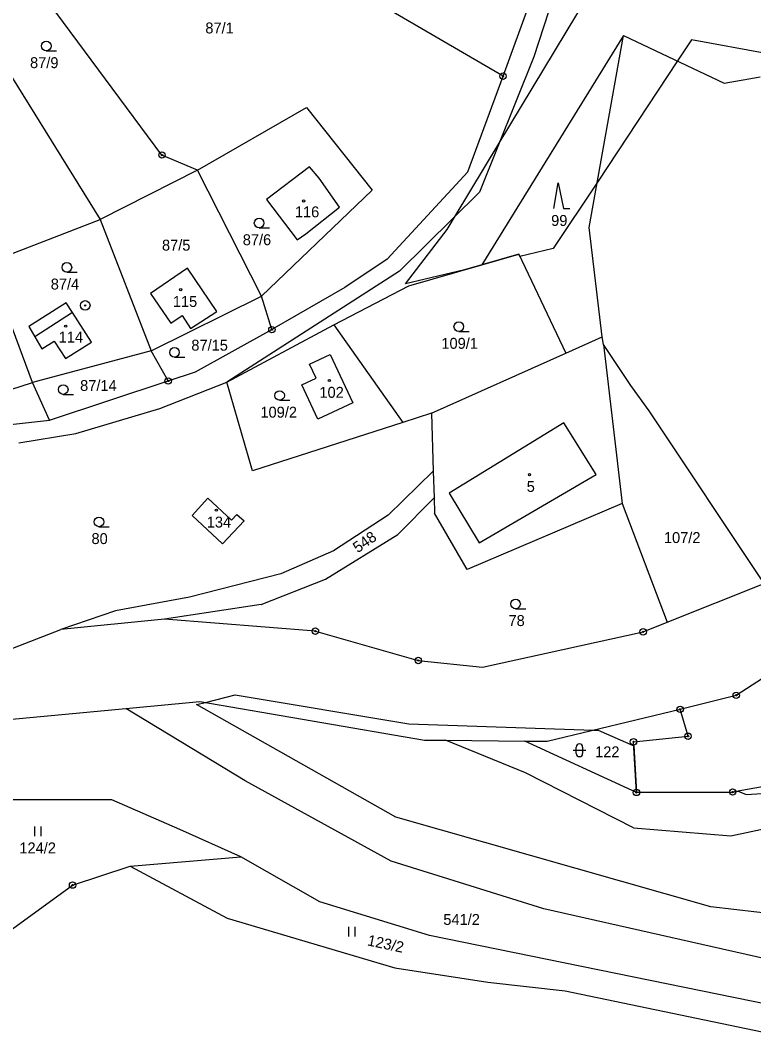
# Model space of a CAD drawing. Extents: x -547623 to -538651, y -1096714 to -1086522.
# Drawn here: x -544594.9 to -544480.8, y -1094558.3 to -1094399.5 of the extents above; entities that cross this region are included whole.
import ezdxf

# ---------------------------------------------------------------- set-up
doc = ezdxf.new("R2010")
doc.units = 0
for name, color, linetype in [('Vrstva 1', 7, 'Continuous'), ('Vrstva 25', 7, 'Continuous'), ('Vrstva 33', 7, 'Continuous'), ('Vrstva 52', 7, 'Continuous'), ('Vrstva 83', 7, 'Continuous'), ('Vrstva 86', 7, 'Continuous'), ('Vrstva 90', 7, 'Continuous'), ('Vrstva 92', 7, 'Continuous')]:
    doc.layers.add(name, color=color, linetype=linetype)

msp = doc.modelspace()

# ---------------------------------------------------------------- linework, layer by layer
at = {"layer": 'Vrstva 1'}
for points in [[(-544519.82, -1094408.15), (-544584.34, -1094370.53)], [(-544572.89, -1094420.43), (-544608.01, -1094373.06)], [(-544610.79, -1094384.91), (-544582.52, -1094430.48)], [(-544509.63, -1094388.53), (-544515.03, -1094405.12)], [(-544519.82, -1094408.15), (-544515.7, -1094396.87)], [(-544501.07, -1094401.8), (-544523.11, -1094437.52)], [(-544506.4, -1094431.69), (-544501.07, -1094401.8)], [(-544501.07, -1094401.8), (-544485.43, -1094409.22)], [(-544515.03, -1094405.12), (-544523.46, -1094426.21)], [(-544525.28, -1094423.07), (-544519.82, -1094408.15)], [(-544485.43, -1094409.22), (-544479.78, -1094408.26)], [(-544567.38, -1094422.79), (-544550.42, -1094413.01)], [(-544550.42, -1094413.01), (-544540.19, -1094425.9)], [(-544567.38, -1094422.79), (-544572.89, -1094420.43)], [(-544567.38, -1094422.79), (-544582.52, -1094430.48)], [(-544557.38, -1094442.38), (-544567.38, -1094422.79)], [(-544549.91, -1094422.26), (-544556.64, -1094427.34)], [(-544548.44, -1094424.01), (-544549.91, -1094422.26)], [(-544525.28, -1094423.07), (-544537.85, -1094436.64)], [(-544545.26, -1094428.53), (-544548.44, -1094424.01)], [(-544540.19, -1094425.9), (-544557.38, -1094442.38)], [(-544523.46, -1094426.21), (-544535.95, -1094438.49)], [(-544556.64, -1094427.34), (-544551.83, -1094433.64)], [(-544550.48, -1094432.72), (-544545.26, -1094428.53)], [(-544600.01, -1094437.2), (-544582.52, -1094430.48)], [(-544582.52, -1094430.48), (-544574.56, -1094450.91)], [(-544551.83, -1094433.64), (-544550.48, -1094432.72)], [(-544504.39, -1094448.76), (-544506.4, -1094431.69)], [(-544523.11, -1094437.52), (-544517.36, -1094435.86)], [(-544517.36, -1094435.86), (-544510.02, -1094451.27)], [(-544593.06, -1094455.85), (-544600.01, -1094437.2)], [(-544537.85, -1094436.64), (-544544.41, -1094441.05)], [(-544534.46, -1094440.81), (-544523.11, -1094437.52)], [(-544568.91, -1094438.07), (-544574.7, -1094442.01)], [(-544564.37, -1094444.77), (-544568.91, -1094438.07)], [(-544535.95, -1094438.49), (-544562.82, -1094455.78)], [(-544544.41, -1094441.05), (-544555.78, -1094447.62)], [(-544546.15, -1094446.85), (-544534.46, -1094440.81)], [(-544574.7, -1094442.01), (-544571.52, -1094446.62)], [(-544574.56, -1094450.91), (-544557.38, -1094442.38)], [(-544555.78, -1094447.62), (-544557.38, -1094442.38)], [(-544587.81, -1094443.46), (-544593.59, -1094447.13)], [(-544586.83, -1094444.97), (-544587.81, -1094443.46)], [(-544583.85, -1094449.59), (-544586.83, -1094444.97)], [(-544571.52, -1094446.62), (-544569.77, -1094445.43)], [(-544569.77, -1094445.43), (-544568.44, -1094447.46)], [(-544568.44, -1094447.46), (-544564.37, -1094444.77)], [(-544593.59, -1094447.13), (-544592.67, -1094448.72)], [(-544562.82, -1094455.78), (-544546.15, -1094446.85)], [(-544546.15, -1094446.85), (-544535.41, -1094462.05)], [(-544592.67, -1094448.72), (-544591.57, -1094450.61)], [(-544567.68, -1094454.21), (-544555.78, -1094447.62)], [(-544510.02, -1094451.27), (-544504.39, -1094448.76)], [(-544504.21, -1094449.91), (-544504.39, -1094448.76)], [(-544591.57, -1094450.61), (-544589.66, -1094449.42)], [(-544589.66, -1094449.42), (-544587.9, -1094452.11)], [(-544587.9, -1094452.11), (-544583.85, -1094449.59)], [(-544499.92, -1094456.3), (-544504.21, -1094449.91)], [(-544504.21, -1094449.91), (-544501.27, -1094474.71)], [(-544574.56, -1094450.91), (-544593.06, -1094455.85)], [(-544571.92, -1094455.61), (-544574.56, -1094450.91)], [(-544549.93, -1094452.99), (-544546.71, -1094451.49)], [(-544546.71, -1094451.49), (-544543.2, -1094459.01)], [(-544530.93, -1094460.6), (-544510.02, -1094451.27)], [(-544548.91, -1094455.17), (-544549.93, -1094452.99)], [(-544571.92, -1094455.61), (-544567.68, -1094454.21)], [(-544551.13, -1094456.2), (-544548.91, -1094455.17)], [(-544611.09, -1094461.67), (-544593.06, -1094455.85)], [(-544590.39, -1094461.72), (-544593.06, -1094455.85)], [(-544590.39, -1094461.72), (-544571.92, -1094455.61)], [(-544573.24, -1094459.92), (-544562.82, -1094455.78)], [(-544558.82, -1094469.62), (-544562.82, -1094455.78)], [(-544548.64, -1094461.55), (-544551.13, -1094456.2)], [(-544497.09, -1094460.28), (-544499.92, -1094456.3)], [(-544586.29, -1094463.78), (-544573.24, -1094459.92)], [(-544543.2, -1094459.01), (-544548.64, -1094461.55)], [(-544530.93, -1094460.6), (-544535.41, -1094462.05)], [(-544530.93, -1094460.6), (-544530.67, -1094469.65)], [(-544479.2, -1094487.13), (-544497.09, -1094460.28)], [(-544604.47, -1094463.25), (-544590.39, -1094461.72)], [(-544535.41, -1094462.05), (-544558.82, -1094469.62)], [(-544595.15, -1094465.22), (-544586.29, -1094463.78)], [(-544530.67, -1094469.65), (-544537.69, -1094476.48)], [(-544530.67, -1094469.65), (-544530.56, -1094473.81)], [(-544568.17, -1094476.55), (-544565.75, -1094473.86)], [(-544565.75, -1094473.86), (-544562.08, -1094477.29)], [(-544536.2, -1094479.53), (-544530.56, -1094473.81)], [(-544530.56, -1094473.81), (-544530.49, -1094476.2)], [(-544501.27, -1094474.71), (-544525.42, -1094484.97)], [(-544501.27, -1094474.71), (-544494.29, -1094493.18)], [(-544563.48, -1094480.98), (-544568.17, -1094476.55)], [(-544560.11, -1094477.38), (-544563.48, -1094480.98)], [(-544562.08, -1094477.29), (-544561.25, -1094476.38)], [(-544561.25, -1094476.38), (-544560.11, -1094477.38)], [(-544537.69, -1094476.48), (-544546.19, -1094482.05)], [(-544525.42, -1094484.97), (-544530.49, -1094476.2)], [(-544547.46, -1094486.48), (-544536.2, -1094479.53)], [(-544546.19, -1094482.05), (-544554.42, -1094485.66)], [(-544554.42, -1094485.66), (-544568.59, -1094489.25)], [(-544557.46, -1094490.39), (-544547.46, -1094486.48)], [(-544494.29, -1094493.18), (-544479.2, -1094487.13)], [(-544568.59, -1094489.25), (-544580.11, -1094491.42)], [(-544580.11, -1094491.42), (-544588.64, -1094494.3)], [(-544557.46, -1094490.39), (-544572.49, -1094492.71)], [(-544572.49, -1094492.71), (-544588.64, -1094494.3)], [(-544549.02, -1094494.56), (-544572.49, -1094492.71)], [(-544498.01, -1094494.67), (-544494.29, -1094493.18)], [(-544609.47, -1094502.39), (-544588.64, -1094494.3)], [(-544549.02, -1094494.56), (-544533, -1094499.13)], [(-544522.99, -1094500.19), (-544498.01, -1094494.67)], [(-544483.53, -1094504.55), (-544472.85, -1094497.6)], [(-544533, -1094499.13), (-544522.99, -1094500.19)], [(-544492.26, -1094506.73), (-544483.53, -1094504.55)], [(-544578.51, -1094506.58), (-544567.02, -1094505.49)], [(-544567.02, -1094505.49), (-544532.04, -1094511.53)], [(-544598.49, -1094508.48), (-544578.51, -1094506.58)], [(-544559.95, -1094517.84), (-544578.51, -1094506.58)], [(-544512.96, -1094511.71), (-544492.26, -1094506.73)], [(-544491.03, -1094510.92), (-544492.26, -1094506.73)], [(-544499.51, -1094511.79), (-544491.03, -1094510.92)], [(-544532.04, -1094511.53), (-544528.77, -1094511.56)], [(-544516.31, -1094516.64), (-544528.77, -1094511.56)], [(-544528.77, -1094511.56), (-544516.44, -1094511.68)], [(-544499.06, -1094519.67), (-544516.44, -1094511.68)], [(-544516.44, -1094511.68), (-544512.96, -1094511.71)], [(-544499.06, -1094519.67), (-544499.51, -1094511.79)], [(-544460.91, -1094515.46), (-544484.09, -1094519.61)], [(-544499.5, -1094525.18), (-544516.31, -1094516.64)], [(-544537.25, -1094530.35), (-544559.95, -1094517.84)], [(-544484.09, -1094519.61), (-544499.06, -1094519.67)], [(-544580.7, -1094520.84), (-544598.37, -1094520.83)], [(-544570.11, -1094525.43), (-544580.7, -1094520.84)], [(-544484.38, -1094526.41), (-544456.89, -1094520.54)], [(-544499.5, -1094525.18), (-544484.38, -1094526.41)], [(-544560.61, -1094529.69), (-544570.11, -1094525.43)], [(-544577.85, -1094531.16), (-544560.61, -1094529.69)], [(-544548.33, -1094536.7), (-544560.61, -1094529.69)], [(-544586.8, -1094534.1), (-544577.85, -1094531.16)], [(-544577.85, -1094531.16), (-544562.76, -1094539.23)], [(-544513.47, -1094537.82), (-544537.25, -1094530.35)], [(-544596.14, -1094540.91), (-544586.8, -1094534.1)], [(-544531.27, -1094541.95), (-544548.33, -1094536.7)], [(-544473.96, -1094546.71), (-544513.47, -1094537.82)], [(-544562.76, -1094539.23), (-544536.63, -1094546.98)], [(-544470.45, -1094554.36), (-544531.27, -1094541.95)], [(-544536.63, -1094546.98), (-544522.17, -1094549.23)], [(-544522.17, -1094549.23), (-544510.16, -1094550.54)], [(-544510.16, -1094550.54), (-544472.99, -1094558.31)]]:
    msp.add_lwpolyline(points, dxfattribs=at)
at = {"layer": 'Vrstva 25'}
for p, q in [((-544590.9, -1094404.2), (-544589.3, -1094404.2)), ((-544557.77, -1094431.77), (-544556.17, -1094431.77)), ((-544587.69, -1094438.67), (-544586.09, -1094438.67)), ((-544526.7, -1094447.9), (-544525.1, -1094447.9)), ((-544570.94, -1094451.9), (-544569.34, -1094451.9)), ((-544588.26, -1094457.69), (-544586.66, -1094457.69)), ((-544554.59, -1094458.62), (-544552.99, -1094458.62)), ((-544582.7, -1094478.3), (-544581.1, -1094478.3)), ((-544517.87, -1094491.07), (-544516.27, -1094491.07)), ((-544508.93, -1094513.1), (-544506.93, -1094513.1)), ((-544508.43, -1094513.6), (-544508.43, -1094512.6)), ((-544507.43, -1094512.6), (-544507.43, -1094513.6)), ((-544592.67, -1094526.46), (-544592.67, -1094524.96)), ((-544591.67, -1094526.46), (-544591.67, -1094524.96)), ((-544543.81, -1094542.11), (-544543.81, -1094540.61)), ((-544542.81, -1094542.11), (-544542.81, -1094540.61))]:
    msp.add_line(p, q, dxfattribs=at)
msp.add_lwpolyline([(-544511.92, -1094428.77), (-544511.22, -1094424.77), (-544510.42, -1094428.77), (-544509.42, -1094428.77)], dxfattribs=at)
for centre, radius in [((-544590.9, -1094403.45), 0.75), ((-544550.85, -1094427.58), 0.175), ((-544557.77, -1094431.02), 0.75), ((-544587.69, -1094437.92), 0.75), ((-544569.97, -1094441.38), 0.175), ((-544587.87, -1094447.08), 0.175), ((-544526.7, -1094447.15), 0.75), ((-544570.94, -1094451.15), 0.75), ((-544588.26, -1094456.94), 0.75), ((-544546.83, -1094455.53), 0.175), ((-544554.59, -1094457.87), 0.75), ((-544515.7, -1094470.18), 0.175), ((-544564.42, -1094475.73), 0.175), ((-544582.7, -1094477.55), 0.75), ((-544517.87, -1094490.32), 0.75)]:
    msp.add_circle(centre, radius, dxfattribs=at)
for centre, start, end in [((-544507.93, -1094512.6), 0, 180), ((-544507.93, -1094513.6), 180, 0)]:
    msp.add_arc(centre, 0.5, start, end, dxfattribs=at)
at = {"layer": 'Vrstva 33'}
for points in [[(-544586.83, -1094444.97), (-544592.67, -1094448.72)], [(-544510.38, -1094462.15), (-544528.21, -1094473.1)], [(-544505.35, -1094470.19), (-544510.38, -1094462.15)], [(-544523.53, -1094480.8), (-544505.35, -1094470.19)], [(-544528.21, -1094473.1), (-544523.53, -1094480.8)]]:
    msp.add_lwpolyline(points, dxfattribs=at)
at = {"layer": 'Vrstva 52'}
for points in [[(-544478.59, -1094404.69), (-544490.5, -1094402.5), (-544492.67, -1094405.78), (-544505.14, -1094424.63), (-544512, -1094435), (-544517.18, -1094436.24), (-544517.36, -1094435.86), (-544523.11, -1094437.52), (-544525.81, -1094438.3), (-544535, -1094440.5), (-544528.5, -1094432), (-544527.27, -1094429.95), (-544520.4, -1094418.56), (-544506.5, -1094395.5)], [(-544386.24, -1094514.68), (-544430, -1094534), (-544466, -1094540), (-544487.5, -1094537.5), (-544536.5, -1094523.5), (-544567.5, -1094506), (-544566.1, -1094505.65), (-544561.5, -1094504.5), (-544534.5, -1094509), (-544505.75, -1094509.97), (-544505, -1094510), (-544499.48, -1094512.4), (-544499.06, -1094519.67), (-544484.09, -1094519.61), (-544483.24, -1094519.46), (-544482, -1094520), (-544458, -1094518.5), (-544392.4, -1094489.67)]]:
    msp.add_lwpolyline(points, dxfattribs=at)
at = {"layer": 'Vrstva 83'}
for centre, radius in [((-544519.82, -1094408.15), 0.5), ((-544519.82, -1094408.15), 0.1), ((-544572.89, -1094420.43), 0.5), ((-544572.89, -1094420.43), 0.1), ((-544584.84, -1094443.85), 0.75), ((-544584.84, -1094443.85), 0.1), ((-544555.78, -1094447.62), 0.5), ((-544555.78, -1094447.62), 0.1), ((-544571.92, -1094455.61), 0.5), ((-544571.92, -1094455.61), 0.1), ((-544549.02, -1094494.56), 0.5), ((-544549.02, -1094494.56), 0.1), ((-544498.01, -1094494.67), 0.5), ((-544498.01, -1094494.67), 0.1), ((-544533, -1094499.13), 0.5), ((-544533, -1094499.13), 0.1), ((-544483.53, -1094504.55), 0.5), ((-544483.53, -1094504.55), 0.1), ((-544492.26, -1094506.73), 0.5), ((-544492.26, -1094506.73), 0.1), ((-544491.03, -1094510.92), 0.5), ((-544491.03, -1094510.92), 0.1), ((-544499.51, -1094511.79), 0.5), ((-544499.51, -1094511.79), 0.1), ((-544499.06, -1094519.67), 0.5), ((-544499.06, -1094519.67), 0.1), ((-544484.09, -1094519.61), 0.5), ((-544484.09, -1094519.61), 0.1), ((-544586.8, -1094534.1), 0.5), ((-544586.8, -1094534.1), 0.1)]:
    msp.add_circle(centre, radius, dxfattribs=at)
at = {"layer": 'Vrstva 90'}
for points in [[(-544549.91, -1094422.26), (-544556.64, -1094427.34)], [(-544548.44, -1094424.01), (-544549.91, -1094422.26)], [(-544545.26, -1094428.53), (-544548.44, -1094424.01)], [(-544556.64, -1094427.34), (-544551.83, -1094433.64)], [(-544550.48, -1094432.72), (-544545.26, -1094428.53)], [(-544551.83, -1094433.64), (-544550.48, -1094432.72)], [(-544568.91, -1094438.07), (-544574.7, -1094442.01)], [(-544564.37, -1094444.77), (-544568.91, -1094438.07)], [(-544574.7, -1094442.01), (-544571.52, -1094446.62)], [(-544586.83, -1094444.97), (-544592.67, -1094448.72)], [(-544583.85, -1094449.59), (-544586.83, -1094444.97)], [(-544571.52, -1094446.62), (-544569.77, -1094445.43)], [(-544569.77, -1094445.43), (-544568.44, -1094447.46)], [(-544568.44, -1094447.46), (-544564.37, -1094444.77)], [(-544592.67, -1094448.72), (-544591.57, -1094450.61)], [(-544591.57, -1094450.61), (-544589.66, -1094449.42)], [(-544589.66, -1094449.42), (-544587.9, -1094452.11)], [(-544587.9, -1094452.11), (-544583.85, -1094449.59)], [(-544549.93, -1094452.99), (-544546.71, -1094451.49)], [(-544546.71, -1094451.49), (-544543.2, -1094459.01)], [(-544548.91, -1094455.17), (-544549.93, -1094452.99)], [(-544551.13, -1094456.2), (-544548.91, -1094455.17)], [(-544548.64, -1094461.55), (-544551.13, -1094456.2)], [(-544543.2, -1094459.01), (-544548.64, -1094461.55)], [(-544510.38, -1094462.15), (-544528.21, -1094473.1)], [(-544505.35, -1094470.19), (-544510.38, -1094462.15)], [(-544523.53, -1094480.8), (-544505.35, -1094470.19)], [(-544568.17, -1094476.55), (-544565.75, -1094473.86)], [(-544565.75, -1094473.86), (-544562.08, -1094477.29)], [(-544528.21, -1094473.1), (-544523.53, -1094480.8)], [(-544563.48, -1094480.98), (-544568.17, -1094476.55)], [(-544560.11, -1094477.38), (-544563.48, -1094480.98)], [(-544562.08, -1094477.29), (-544561.25, -1094476.38)], [(-544561.25, -1094476.38), (-544560.11, -1094477.38)]]:
    msp.add_lwpolyline(points, dxfattribs=at)

# ---------------------------------------------------------------- texts
at = {"layer": 'Vrstva 86'}
for s, p in [('87/1', (-544566.14, -1094401.5)), ('87/9', (-544593.42, -1094406.9)), ('99', (-544512.33, -1094431.47)), ('87/6', (-544560.32, -1094434.47)), ('87/5', (-544572.89, -1094435.31)), ('87/4', (-544590.2, -1094441.37)), ('109/1', (-544529.41, -1094450.6)), ('87/15', (-544568.32, -1094450.89)), ('87/14', (-544585.63, -1094457.17)), ('109/2', (-544557.57, -1094461.32)), ('107/2', (-544494.78, -1094480.84)), ('80', (-544583.86, -1094481)), ('78', (-544518.97, -1094493.77)), ('122', (-544505.49, -1094514.2)), ('124/2', (-544595.08, -1094529.16)), ('541/2', (-544529.11, -1094540.3))]:
    msp.add_text(s, height=1.7, dxfattribs=at).set_placement(p)
for s, rotation, p in [('548', 35.0082, (-544542.43, -1094482.45)), ('123/2', 348.0463, (-544541.03, -1094543.47))]:
    msp.add_text(s, height=1.7, rotation=rotation, dxfattribs=at).set_placement(p)
at = {"layer": 'Vrstva 92'}
for s, p in [('116', (-544552.21, -1094430.13)), ('115', (-544571.2, -1094444.08)), ('114', (-544588.97, -1094449.62)), ('102', (-544548.39, -1094458.23)), ('5', (-544516.13, -1094472.88)), ('134', (-544565.92, -1094478.43))]:
    msp.add_text(s, height=1.7, dxfattribs=at).set_placement(p)

doc.saveas('drawing.dxf')
